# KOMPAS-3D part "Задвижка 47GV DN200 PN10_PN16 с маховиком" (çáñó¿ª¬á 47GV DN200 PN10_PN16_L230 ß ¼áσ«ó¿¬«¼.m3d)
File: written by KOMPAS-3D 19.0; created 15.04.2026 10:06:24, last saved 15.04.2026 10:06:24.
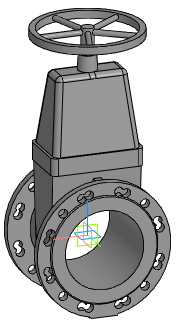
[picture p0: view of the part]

Document properties: Автор: Евгений; Полное имя файла: Z:\3.Личные\kachalov\3d для проектировщиков\2.1 Тип 47GV, 47GV.Z\Задвижка 47GV_DN40-DN600\stp_Задвижка 47GV\Задвижка 47GV DN200 PN10_PN16_L230 с маховиком.m3d

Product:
- Part/product: Задвижка 47GV DN200 PN10_PN16 с маховиком

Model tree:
1. Операция без истории:1  (labels: Задвижка 47GV DN200 PN10_PN16 с маховиком)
